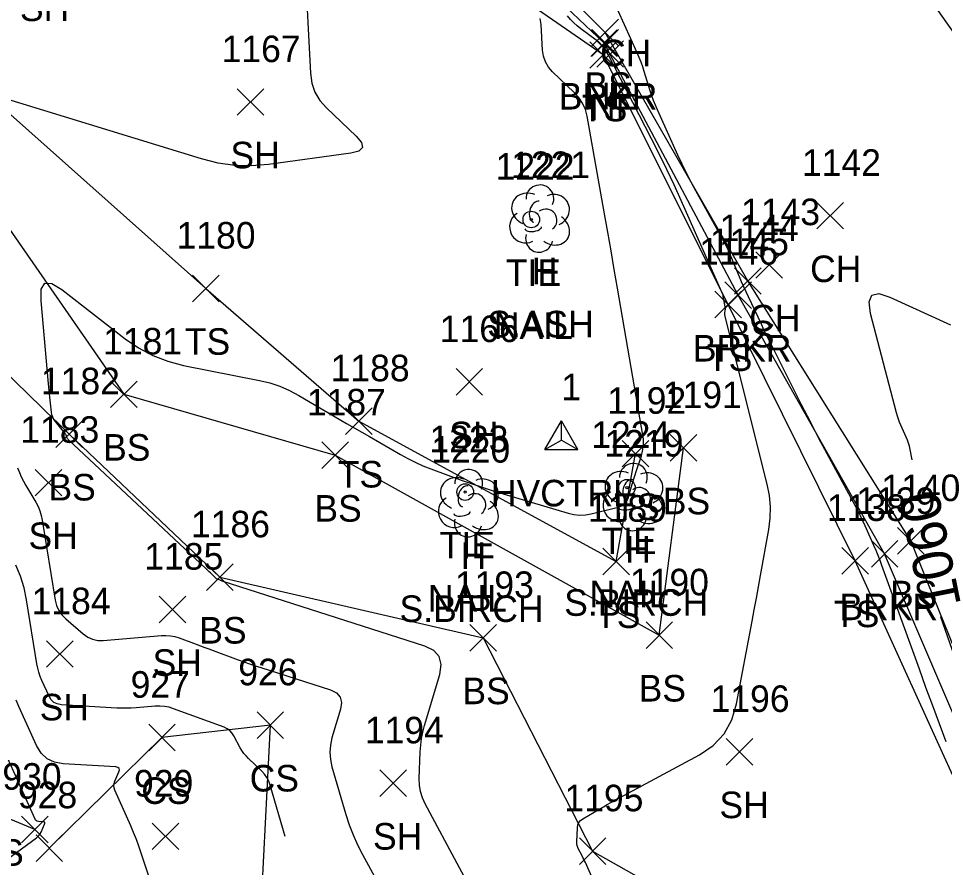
# Model space of a CAD drawing. Extents: x 1592612 to 1596497, y 111838 to 113741.
# Drawn here: x 1592722.3 to 1592792, y 113603.3 to 113667.2 of the extents above; entities that cross this region are included whole.
import ezdxf

# ---------------------------------------------------------------- set-up
doc = ezdxf.new("R2010")
doc.units = 0
for name, color, linetype in [('C_A', 7, 'Continuous'), ('C_C', 7, 'Continuous'), ('C_I', 7, 'Continuous'), ('CBP', 7, 'Continuous'), ('CPSM', 7, 'Continuous'), ('L_A', 7, 'Continuous'), ('L_C', 7, 'Continuous'), ('L_I', 7, 'Continuous'), ('L_TIC', 7, 'Continuous'), ('LAWE', 7, 'Continuous'), ('LELB', 7, 'Continuous'), ('LSOGCMA', 7, 'Continuous'), ('LSOGCMA_T', 7, 'Continuous'), ('LSOGCMI', 7, 'Continuous'), ('LTD', 7, 'Continuous'), ('LWS', 7, 'Continuous')]:
    doc.layers.add(name, color=color, linetype=linetype)

msp = doc.modelspace()

# ---------------------------------------------------------------- linework, layer by layer
at = {"layer": 'CBP'}
for centre, radius in [((1592760.904, 113652.058), 0.625), ((1592760.904, 113652.058), 0.0833), ((1592755.926, 113631.531), 0.625), ((1592768.105, 113631.854), 0.625), ((1592768.105, 113631.854), 0.0833), ((1592755.926, 113631.531), 0.0833)]:
    msp.add_circle(centre, radius, dxfattribs=at)
at = {"layer": 'CPSM'}
for p, q in [((1592761.919, 113634.729), (1592763.169, 113636.894)), ((1592764.419, 113634.729), (1592763.169, 113636.894)), ((1592763.169, 113635.45), (1592763.169, 113636.894)), ((1592761.919, 113634.729), (1592763.169, 113635.45)), ((1592763.169, 113635.45), (1592763.169, 113635.45)), ((1592763.169, 113635.45), (1592764.419, 113634.729)), ((1592761.919, 113634.729), (1592764.419, 113634.729))]:
    msp.add_line(p, q, dxfattribs=at)
at = {"layer": 'L_TIC'}
for points in [[(1592765.461, 113665.146), (1592767.461, 113667.146)], [(1592767.461, 113665.146), (1592765.461, 113667.146)], [(1592765.38, 113664.342), (1592767.38, 113666.342)], [(1592767.38, 113664.342), (1592765.38, 113666.342)], [(1592765.472, 113664.357), (1592767.472, 113666.357)], [(1592767.472, 113664.357), (1592765.472, 113666.357)], [(1592765.309, 113663.453), (1592767.309, 113665.453)], [(1592767.309, 113663.453), (1592765.309, 113665.453)], [(1592765.841, 113663.52), (1592767.841, 113665.52)], [(1592767.841, 113663.52), (1592765.841, 113665.52)], [(1592738.755, 113659.911), (1592740.755, 113661.911)], [(1592740.755, 113659.911), (1592738.755, 113661.911)], [(1592782.413, 113651.345), (1592784.413, 113653.345)], [(1592784.413, 113651.345), (1592782.413, 113653.345)], [(1592777.824, 113647.632), (1592779.824, 113649.632)], [(1592779.824, 113647.632), (1592777.824, 113649.632)], [(1592776.21, 113646.427), (1592778.21, 113648.427)], [(1592778.21, 113646.427), (1592776.21, 113648.427)], [(1592735.398, 113645.87), (1592737.398, 113647.87)], [(1592737.398, 113645.87), (1592735.398, 113647.87)], [(1592775.477, 113645.362), (1592777.477, 113647.362)], [(1592777.477, 113645.362), (1592775.477, 113647.362)], [(1592774.723, 113644.654), (1592776.723, 113646.654)], [(1592776.723, 113644.654), (1592774.723, 113646.654)], [(1592755.238, 113638.828), (1592757.238, 113640.828)], [(1592757.238, 113638.828), (1592755.238, 113640.828)], [(1592729.214, 113637.893), (1592731.214, 113639.893)], [(1592731.214, 113637.893), (1592729.214, 113639.893)], [(1592746.918, 113635.873), (1592748.918, 113637.873)], [(1592748.918, 113635.873), (1592746.918, 113637.873)], [(1592725.097, 113634.895), (1592727.097, 113636.895)], [(1592727.097, 113634.895), (1592725.097, 113636.895)], [(1592767.748, 113633.425), (1592769.748, 113635.425)], [(1592769.748, 113633.425), (1592767.748, 113635.425)], [(1592771.366, 113633.853), (1592773.366, 113635.853)], [(1592773.366, 113633.853), (1592771.366, 113635.853)], [(1592745.126, 113633.301), (1592747.126, 113635.301)], [(1592747.126, 113633.301), (1592745.126, 113635.301)], [(1592723.547, 113631.239), (1592725.547, 113633.239)], [(1592725.547, 113631.239), (1592723.547, 113633.239)], [(1592788.48, 113626.849), (1592790.48, 113628.849)], [(1592790.48, 113626.849), (1592788.48, 113628.849)], [(1592786.513, 113625.88), (1592788.513, 113627.88)], [(1592788.513, 113625.88), (1592786.513, 113627.88)], [(1592766.3, 113625.295), (1592768.3, 113627.295)], [(1592768.3, 113625.295), (1592766.3, 113627.295)], [(1592784.293, 113625.354), (1592786.293, 113627.354)], [(1592786.293, 113625.354), (1592784.293, 113627.354)], [(1592736.453, 113624.119), (1592738.453, 113626.119)], [(1592738.453, 113624.119), (1592736.453, 113626.119)], [(1592732.89, 113621.685), (1592734.89, 113623.685)], [(1592734.89, 113621.685), (1592732.89, 113623.685)], [(1592756.272, 113619.552), (1592758.272, 113621.552)], [(1592758.272, 113619.552), (1592756.272, 113621.552)], [(1592769.546, 113619.752), (1592771.546, 113621.752)], [(1592771.546, 113619.752), (1592769.546, 113621.752)], [(1592724.393, 113618.332), (1592726.393, 113620.332)], [(1592726.393, 113618.332), (1592724.393, 113620.332)], [(1592740.254, 113612.977), (1592742.254, 113614.977)], [(1592742.254, 113612.977), (1592740.254, 113614.977)], [(1592732.09, 113612.041), (1592734.09, 113614.041)], [(1592734.09, 113612.041), (1592732.09, 113614.041)], [(1592775.587, 113610.968), (1592777.587, 113612.968)], [(1592777.587, 113610.968), (1592775.587, 113612.968)], [(1592749.494, 113608.601), (1592751.494, 113610.601)], [(1592751.494, 113608.601), (1592749.494, 113610.601)], [(1592722.518, 113605.111), (1592724.518, 113607.111)], [(1592724.518, 113605.111), (1592722.518, 113607.111)], [(1592732.36, 113604.599), (1592734.36, 113606.599)], [(1592734.36, 113604.599), (1592732.36, 113606.599)], [(1592723.603, 113603.715), (1592725.603, 113605.715)], [(1592725.603, 113603.715), (1592723.603, 113605.715)], [(1592764.525, 113603.487), (1592766.525, 113605.487)], [(1592766.525, 113603.487), (1592764.525, 113605.487)]]:
    msp.add_lwpolyline(points, dxfattribs=at)
at = {"layer": 'LAWE'}
msp.add_lwpolyline([(1592867.645, 113460.38), (1592859.409, 113477.515), (1592844.793, 113495.549), (1592832.37, 113516.6), (1592826.928, 113530.545), (1592818.762, 113547.936), (1592807.597, 113581.108), (1592797.669, 113603.177), (1592787.513, 113626.88), (1592776.477, 113646.362), (1592766.38, 113665.342), (1592748.736, 113682.085), (1592730.356, 113695.945)], dxfattribs=at)
at = {"layer": 'LELB'}
for points in [[(1592869.098, 113460.398), (1592860.441, 113478.115), (1592844.631, 113496.556), (1592834.165, 113516.964), (1592828.396, 113531.171), (1592823.559, 113549.918), (1592808.456, 113581.723), (1592799.527, 113603.061), (1592789.48, 113627.849), (1592777.21, 113647.427), (1592766.461, 113666.146), (1592749.422, 113683.288), (1592730.933, 113697.021)], [(1592856.492, 113476.867), (1592843.193, 113495.045), (1592831.688, 113516.664), (1592823.204, 113528.692), (1592814.853, 113545.459), (1592806.797, 113580.845), (1592796.452, 113601.854), (1592785.293, 113626.354), (1592775.723, 113645.654), (1592766.309, 113664.453), (1592745.043, 113679.184), (1592727.847, 113694.217)], [(1592709.84, 113681.357), (1592717.065, 113664.051), (1592736.398, 113646.87), (1592747.918, 113636.873), (1592767.3, 113626.295), (1592768.748, 113634.425)], [(1592705.057, 113678.307), (1592714.096, 113662.114), (1592730.214, 113638.893), (1592746.126, 113634.3), (1592770.546, 113620.752), (1592772.366, 113634.853)], [(1592701.588, 113659.774), (1592726.097, 113635.895), (1592737.453, 113625.119), (1592757.272, 113620.552), (1592765.525, 113604.487), (1592785.217, 113593.362), (1592785.143, 113579.955), (1592783.097, 113567.939), (1592785.828, 113560.008), (1592797.4, 113544.62), (1592809.213, 113533.643), (1592811.425, 113524.524), (1592820.841, 113522.69), (1592826.429, 113512.914)], [(1592733.8, 113592.586), (1592740.378, 113596.74), (1592741.254, 113613.977), (1592733.09, 113613.041), (1592724.603, 113604.715)]]:
    msp.add_lwpolyline(points, dxfattribs=at)
at = {"layer": 'LSOGCMA'}
for points in [[(1592789.576, 113633.948), (1592789.433, 113634.735), (1592789.382, 113634.975), (1592789.316, 113635.211), (1592789.236, 113635.442), (1592789.141, 113635.669), (1592788.732, 113636.567), (1592788.635, 113636.793), (1592788.548, 113637.023), (1592788.471, 113637.256), (1592788.404, 113637.493), (1592786.456, 113644.984), (1592786.339, 113645.863), (1592786.542, 113646.36), (1592787.067, 113646.476), (1592787.913, 113646.209), (1592792.467, 113644.137)], [(1592742.366, 113605.578), (1592741.233, 113609.455), (1592741.127, 113609.749), (1592740.985, 113610.022), (1592740.809, 113610.274), (1592740.598, 113610.504), (1592739.595, 113611.468), (1592739.418, 113611.652), (1592739.257, 113611.848), (1592739.111, 113612.056), (1592738.982, 113612.276), (1592738.494, 113613.18), (1592738.357, 113613.389), (1592738.191, 113613.564), (1592737.995, 113613.704), (1592737.769, 113613.81), (1592733.967, 113615.212), (1592733.626, 113615.317), (1592733.28, 113615.384), (1592732.929, 113615.412), (1592732.573, 113615.402), (1592731.138, 113615.282), (1592730.779, 113615.259), (1592730.42, 113615.248), (1592730.061, 113615.251), (1592729.701, 113615.265), (1592725.512, 113615.513), (1592725.208, 113615.567), (1592724.953, 113615.692), (1592724.745, 113615.886), (1592724.586, 113616.149), (1592724.044, 113617.345), (1592723.919, 113617.647), (1592723.814, 113617.955), (1592723.731, 113618.269), (1592723.668, 113618.59), (1592722.89, 113623.418), (1592722.702, 113624.316), (1592722.434, 113625.185), (1592722.084, 113626.025)], [(1592797.582, 113605.486), (1592791.75, 113622.113), (1592791.741, 113622.143)]]:
    msp.add_lwpolyline(points, dxfattribs=at)
at = {"layer": 'LSOGCMI'}
for points in [[(1592788.325, 113672.344), (1592793.937, 113664.383)], [(1592743.845, 113671.231), (1592744.267, 113663.072), (1592744.372, 113662.328), (1592744.608, 113661.644), (1592744.975, 113661.021), (1592745.473, 113660.458), (1592747.724, 113658.327), (1592748.12, 113657.847), (1592748.184, 113657.475), (1592747.915, 113657.21), (1592747.314, 113657.052), (1592741.123, 113656.21), (1592739.841, 113656.104), (1592738.57, 113656.137), (1592737.31, 113656.31), (1592736.062, 113656.622), (1592720.725, 113661.329)], [(1592792.151, 113612.707), (1592791.639, 113614.073), (1592791.132, 113615.441), (1592790.629, 113616.811), (1592790.131, 113618.182), (1592787.307, 113626.001), (1592787.166, 113626.382), (1592787.018, 113626.761), (1592786.864, 113627.136), (1592786.703, 113627.51), (1592786.045, 113628.997), (1592785.877, 113629.367), (1592785.702, 113629.734), (1592785.52, 113630.096), (1592785.33, 113630.456), (1592783.017, 113634.74), (1592782.57, 113635.574), (1592782.129, 113636.412), (1592781.694, 113637.253), (1592781.264, 113638.097), (1592779.14, 113642.31), (1592778.908, 113642.773), (1592778.679, 113643.238), (1592778.454, 113643.704), (1592778.231, 113644.171), (1592777.258, 113646.227), (1592777.082, 113646.604), (1592776.911, 113646.983), (1592776.744, 113647.365), (1592776.582, 113647.748), (1592775.942, 113649.285), (1592775.776, 113649.667), (1592775.6, 113650.044), (1592775.413, 113650.415), (1592775.215, 113650.781), (1592773.292, 113654.215), (1592772.932, 113654.875), (1592772.587, 113655.543), (1592772.256, 113656.217), (1592771.939, 113656.9), (1592770.397, 113660.32), (1592770.246, 113660.669), (1592770.106, 113661.022), (1592769.977, 113661.38), (1592769.86, 113661.742), (1592769.412, 113663.197), (1592769.295, 113663.559), (1592769.166, 113663.916), (1592769.026, 113664.269), (1592768.875, 113664.618), (1592767.447, 113667.774)], [(1592758.081, 113598.41), (1592752.906, 113608.054), (1592752.7, 113608.506), (1592752.558, 113608.972), (1592752.481, 113609.453), (1592752.467, 113609.949), (1592752.542, 113611.963), (1592752.576, 113612.464), (1592752.641, 113612.96), (1592752.737, 113613.451), (1592752.865, 113613.937), (1592754.005, 113617.797), (1592754.113, 113618.533), (1592753.962, 113619.132), (1592753.552, 113619.594), (1592752.883, 113619.92), (1592737.621, 113624.831), (1592737.582, 113624.843), (1592737.543, 113624.857), (1592737.504, 113624.87), (1592737.465, 113624.884), (1592737.311, 113624.941), (1592737.273, 113624.957), (1592737.238, 113624.977), (1592737.205, 113625), (1592737.174, 113625.026), (1592736.732, 113625.449), (1592736.648, 113625.529), (1592736.564, 113625.609), (1592736.48, 113625.688), (1592736.396, 113625.768), (1592726.021, 113635.498), (1592725.99, 113635.53), (1592725.964, 113635.566), (1592725.942, 113635.604), (1592725.925, 113635.645), (1592725.866, 113635.816), (1592725.849, 113635.858), (1592725.829, 113635.898), (1592725.806, 113635.936), (1592725.779, 113635.971), (1592725.067, 113636.837), (1592724.952, 113636.998), (1592724.864, 113637.171), (1592724.802, 113637.354), (1592724.767, 113637.549), (1592724.647, 113638.673), (1592724.62, 113638.928), (1592724.594, 113639.182), (1592724.57, 113639.437), (1592724.546, 113639.691), (1592723.98, 113645.922), (1592724.003, 113646.818), (1592724.273, 113647.26), (1592724.791, 113647.249), (1592725.557, 113646.783), (1592730.32, 113643.078), (1592731.329, 113642.381), (1592732.397, 113641.814), (1592733.524, 113641.378), (1592734.711, 113641.071), (1592740.431, 113639.934), (1592741.208, 113639.745), (1592741.962, 113639.495), (1592742.692, 113639.181), (1592743.398, 113638.805), (1592746.422, 113637.032), (1592746.993, 113636.698), (1592747.564, 113636.365), (1592748.136, 113636.034), (1592748.709, 113635.703), (1592751.051, 113634.355), (1592751.605, 113634.051), (1592752.17, 113633.772), (1592752.747, 113633.517), (1592753.335, 113633.286), (1592755.709, 113632.411), (1592756.304, 113632.197), (1592756.902, 113631.991), (1592757.503, 113631.795), (1592758.107, 113631.608), (1592763.675, 113629.928), (1592764.11, 113629.828), (1592764.546, 113629.788), (1592764.984, 113629.809), (1592765.423, 113629.89), (1592767.546, 113630.429), (1592767.779, 113630.518), (1592767.967, 113630.655), (1592768.108, 113630.839), (1592768.203, 113631.07), (1592768.498, 113632.12), (1592768.568, 113632.359), (1592768.64, 113632.598), (1592768.715, 113632.835), (1592768.794, 113633.072), (1592769.199, 113634.264), (1592769.234, 113634.376), (1592769.262, 113634.49), (1592769.284, 113634.606), (1592769.299, 113634.723), (1592769.348, 113635.194), (1592769.356, 113635.312), (1592769.356, 113635.429), (1592769.348, 113635.546), (1592769.332, 113635.663), (1592767.398, 113646.894), (1592767.156, 113648.296), (1592766.911, 113649.697), (1592766.665, 113651.097), (1592766.416, 113652.498), (1592765.107, 113659.841), (1592764.975, 113660.349), (1592764.77, 113660.818), (1592764.491, 113661.247), (1592764.138, 113661.636), (1592762.501, 113663.186), (1592762.191, 113663.538), (1592761.962, 113663.927), (1592761.814, 113664.353), (1592761.749, 113664.817), (1592761.649, 113666.75), (1592761.579, 113667.208)], [(1592766.646, 113599.856), (1592764.98, 113603.628), (1592764.921, 113603.758), (1592764.86, 113603.887), (1592764.796, 113604.014), (1592764.73, 113604.141), (1592764.46, 113604.644), (1592764.402, 113604.771), (1592764.362, 113604.903), (1592764.34, 113605.04), (1592764.336, 113605.18), (1592764.375, 113606.243), (1592764.407, 113606.454), (1592764.485, 113606.637), (1592764.609, 113606.793), (1592764.78, 113606.921), (1592766.055, 113607.671), (1592766.332, 113607.833), (1592766.612, 113607.992), (1592766.893, 113608.148), (1592767.175, 113608.302), (1592773.564, 113611.744), (1592774.609, 113612.452), (1592775.424, 113613.327), (1592776.01, 113614.37), (1592776.367, 113615.581), (1592777.534, 113621.808), (1592777.695, 113622.669), (1592777.854, 113623.53), (1592778.012, 113624.391), (1592778.169, 113625.253), (1592778.793, 113628.699), (1592778.903, 113629.559), (1592778.92, 113630.417), (1592778.845, 113631.27), (1592778.678, 113632.121), (1592775.506, 113644.746), (1592775.494, 113644.804), (1592775.487, 113644.862), (1592775.485, 113644.921), (1592775.489, 113644.98), (1592775.514, 113645.224), (1592775.518, 113645.28), (1592775.518, 113645.335), (1592775.514, 113645.391), (1592775.506, 113645.447), (1592775.468, 113645.669), (1592775.458, 113645.724), (1592775.449, 113645.78), (1592775.439, 113645.835), (1592775.429, 113645.891), (1592775.361, 113646.271), (1592775.344, 113646.352), (1592775.322, 113646.432), (1592775.296, 113646.51), (1592775.264, 113646.587), (1592772.191, 113653.497), (1592771.659, 113654.671), (1592771.11, 113655.836), (1592770.545, 113656.993), (1592769.963, 113658.142), (1592766.692, 113664.493), (1592766.512, 113664.798), (1592766.302, 113665.078), (1592766.06, 113665.331), (1592765.788, 113665.559), (1592764.639, 113666.416), (1592764.36, 113666.639), (1592764.097, 113666.878), (1592763.851, 113667.135), (1592763.621, 113667.409)], [(1592722.22, 113633.354), (1592722.349, 113633.01), (1592722.494, 113632.675), (1592722.656, 113632.347), (1592722.835, 113632.027), (1592723.585, 113630.762), (1592723.756, 113630.44), (1592723.895, 113630.107), (1592724.001, 113629.761), (1592724.076, 113629.405), (1592725.045, 113623.392), (1592725.146, 113622.983), (1592725.313, 113622.61), (1592725.544, 113622.274), (1592725.84, 113621.975), (1592727.153, 113620.849), (1592727.494, 113620.607), (1592727.861, 113620.444), (1592728.254, 113620.361), (1592728.672, 113620.357), (1592733.049, 113620.721), (1592733.388, 113620.731), (1592733.722, 113620.704), (1592734.051, 113620.64), (1592734.376, 113620.54), (1592735.662, 113620.066), (1592735.984, 113619.947), (1592736.306, 113619.828), (1592736.628, 113619.71), (1592736.949, 113619.591), (1592738.838, 113618.896), (1592739.26, 113618.743), (1592739.685, 113618.594), (1592740.11, 113618.45), (1592740.538, 113618.31), (1592745.779, 113616.624), (1592746.23, 113616.404), (1592746.507, 113616.092), (1592746.609, 113615.687), (1592746.536, 113615.19), (1592745.894, 113613.018), (1592745.774, 113612.474), (1592745.733, 113611.931), (1592745.772, 113611.387), (1592745.891, 113610.844), (1592746.945, 113607.236), (1592747.194, 113606.462), (1592747.484, 113605.704), (1592747.814, 113604.964), (1592748.184, 113604.24), (1592751.46, 113598.245)], [(1592733.205, 113599.295), (1592731.532, 113604.332), (1592731.352, 113604.853), (1592731.159, 113605.37), (1592730.955, 113605.882), (1592730.737, 113606.389), (1592729.55, 113609.074), (1592729.493, 113609.246), (1592729.473, 113609.419), (1592729.492, 113609.591), (1592729.548, 113609.764), (1592729.848, 113610.456), (1592729.89, 113610.609), (1592729.866, 113610.721), (1592729.777, 113610.793), (1592729.621, 113610.824), (1592725.65, 113611.059), (1592724.993, 113611.177), (1592724.439, 113611.446), (1592723.99, 113611.866), (1592723.644, 113612.438), (1592722.305, 113615.391), (1592722.11, 113615.861)], [(1592721.015, 113603.555), (1592723.644, 113605.489), (1592723.75, 113605.578), (1592723.842, 113605.679), (1592723.92, 113605.791), (1592723.984, 113605.915), (1592724.249, 113606.528), (1592724.269, 113606.6), (1592724.258, 113606.654), (1592724.216, 113606.688), (1592724.142, 113606.702), (1592723.785, 113606.724), (1592723.702, 113606.738), (1592723.632, 113606.772), (1592723.576, 113606.825), (1592723.532, 113606.897), (1592720.074, 113614.523)]]:
    msp.add_lwpolyline(points, dxfattribs=at)
at = {"layer": 'LTD'}
for p, q in [((1592761.508, 113652.18), (1592761.508, 113652.18)), ((1592761.508, 113652.18), (1592761.508, 113652.18)), ((1592756.147, 113630.745), (1592756.147, 113630.745)), ((1592756.147, 113630.745), (1592756.147, 113630.745)), ((1592768.546, 113631.208), (1592768.546, 113631.208)), ((1592768.546, 113631.208), (1592768.546, 113631.208))]:
    msp.add_line(p, q, dxfattribs=at)
for centre in [(1592761.554, 113653.614), (1592768.593, 113632.642), (1592756.194, 113632.179)]:
    msp.add_arc(centre, 1.047, 335.52715, 180.95627, dxfattribs=at)
for centre, major_axis, ratio, start_param, end_param in [((1592760.716, 113652.847), (1.21, -0.512), 0.895232, 1.570796, 4.712389), ((1592762.549, 113652.764), (-1.141, -0.483), 0.949671, 1.570796, 4.712389), ((1592761.299, 113652.638), (-0.208, -0.792), 0.645439, 3.141593, 6.283185), ((1592762.008, 113652.014), (-0.5, 0.667), 0.989748, 3.141593, 6.283185), ((1592760.424, 113651.472), (0.584, -1.042), 0.959034, 3.141593, 6.283185), ((1592762.508, 113651.347), (-1.09, 0.792), 0.841452, 1.570796, 4.712389), ((1592761.049, 113651.43), (-0.625, -0.083), 0.423636, 0, 3.141593), ((1592761.508, 113650.68), (0.265, 1.061), 0.942809, 1.570796, 4.712389), ((1592755.355, 113631.412), (1.21, -0.512), 0.895232, 1.570796, 4.712389), ((1592757.188, 113631.329), (-1.141, -0.483), 0.949671, 1.570796, 4.712389), ((1592767.754, 113631.875), (1.21, -0.512), 0.895232, 1.570796, 4.712389), ((1592769.588, 113631.792), (-1.141, -0.483), 0.949671, 1.570796, 4.712389), ((1592755.938, 113631.204), (-0.208, -0.792), 0.645439, 3.141593, 6.283185), ((1592768.338, 113631.667), (-0.208, -0.792), 0.645439, 3.141593, 6.283185), ((1592769.046, 113631.042), (-0.5, 0.667), 0.989748, 3.141593, 6.283185), ((1592756.647, 113630.579), (-0.5, 0.667), 0.989748, 3.141593, 6.283185), ((1592767.463, 113630.5), (0.584, -1.042), 0.959034, 3.141593, 6.283185), ((1592769.546, 113630.375), (-1.09, 0.792), 0.841452, 1.570796, 4.712389), ((1592755.064, 113630.037), (0.584, -1.042), 0.959034, 3.141593, 6.283185), ((1592757.147, 113629.912), (-1.09, 0.792), 0.841452, 1.570796, 4.712389), ((1592768.088, 113630.458), (-0.625, -0.083), 0.423636, 0, 3.141593), ((1592755.689, 113629.995), (-0.625, -0.083), 0.423636, 0, 3.141593), ((1592768.546, 113629.708), (0.265, 1.061), 0.942809, 1.570796, 4.712389), ((1592756.147, 113629.245), (0.265, 1.061), 0.942809, 1.570796, 4.712389)]:
    msp.add_ellipse(centre, major_axis=major_axis, ratio=ratio, start_param=start_param, end_param=end_param, dxfattribs=at)
at = {"layer": 'LWS'}
msp.add_lwpolyline([(1592723.518, 113606.111), (1592718.067, 113608.381), (1592705.094, 113621.183)], dxfattribs=at)

# ---------------------------------------------------------------- texts
at = {"layer": 'C_A'}
for s, p in [('TIE', (1592758.983, 113647.058)), ('HVCTRL', (1592757.862, 113630.45)), ('TIE', (1592754.005, 113626.531)), ('TIE', (1592766.184, 113626.854))]:
    msp.add_text(s, height=2, dxfattribs=at).set_placement(p)
at = {"layer": 'C_C'}
for p in [(1592758.085, 113643.058), (1592753.108, 113622.531), (1592765.287, 113622.854)]:
    msp.add_text('NAIL', height=2, dxfattribs=at).set_placement(p)
at = {"layer": 'C_I'}
for s, p in [('1222', (1592758.211, 113655.058)), ('1', (1592763.169, 113638.45)), ('1224', (1592765.413, 113634.854)), ('1223', (1592753.234, 113634.531))]:
    msp.add_text(s, height=2, dxfattribs=at).set_placement(p)
at = {"layer": 'L_A'}
for s, p in [('SH', (1592722.39, 113667.003)), ('CH', (1592766.079, 113663.601)), ('BS', (1592764.902, 113661.146)), ('BRKR', (1592762.971, 113660.342)), ('NF', (1592764.952, 113660.357)), ('TS', (1592764.718, 113659.453)), ('NF', (1592765.321, 113659.52)), ('SH', (1592738.243, 113655.911)), ('CH', (1592781.901, 113647.345)), ('H', (1592760.941, 113647.18)), ('CH', (1592777.313, 113643.632)), ('TS', (1592734.808, 113641.87)), ('BS', (1592775.651, 113642.427)), ('BRKR', (1592773.068, 113641.362)), ('TS', (1592774.133, 113640.654)), ('SH', (1592754.726, 113634.828)), ('BS', (1592728.655, 113633.893)), ('TS', (1592746.328, 113631.873)), ('BS', (1592724.538, 113630.895)), ('BS', (1592744.567, 113629.301)), ('TS', (1592767.157, 113629.425)), ('BS', (1592770.807, 113629.853)), ('SH', (1592723.036, 113627.239)), ('H', (1592755.58, 113625.745)), ('H', (1592767.979, 113626.208)), ('BS', (1592787.921, 113622.849)), ('BRKR', (1592784.104, 113621.88)), ('TS', (1592765.709, 113621.295)), ('TS', (1592783.702, 113621.354)), ('BS', (1592735.894, 113620.119)), ('SH', (1592732.379, 113617.685)), ('BS', (1592755.713, 113615.552)), ('BS', (1592768.987, 113615.752)), ('SH', (1592723.881, 113614.332)), ('CS', (1592739.695, 113608.977)), ('CS', (1592731.531, 113608.041)), ('SH', (1592775.075, 113606.968)), ('SH', (1592748.982, 113604.601)), ('WALLS', (1592713.611, 113603.381))]:
    msp.add_text(s, height=2, dxfattribs=at).set_placement(p)
at = {"layer": 'L_C'}
for s, p in [('S.ASH', (1592757.586, 113643.18)), ('S.BIRCH', (1592750.981, 113621.745)), ('S.BIRCH', (1592763.381, 113622.208))]:
    msp.add_text(s, height=2, dxfattribs=at).set_placement(p)
at = {"layer": 'L_I'}
for s, p in [('1167', (1592737.581, 113663.911)), ('1221', (1592759.382, 113655.18)), ('1142', (1592781.287, 113655.345)), ('1143', (1592776.699, 113651.632)), ('1144', (1592775.084, 113650.427)), ('1180', (1592734.186, 113649.87)), ('1145', (1592774.351, 113649.362)), ('1146', (1592773.542, 113648.654)), ('1166', (1592754.009, 113642.828)), ('1181', (1592728.655, 113641.893)), ('1188', (1592745.792, 113639.873)), ('1182', (1592723.971, 113638.895)), ('1191', (1592770.807, 113637.853)), ('1187', (1592744, 113637.301)), ('1192', (1592766.622, 113637.425)), ('1183', (1592722.422, 113635.239)), ('1219', (1592766.412, 113634.208)), ('1220', (1592753.367, 113633.745)), ('1140', (1592787.268, 113630.849)), ('1189', (1592765.166, 113629.295)), ('1138', (1592783.167, 113629.354)), ('1139', (1592785.379, 113629.88)), ('1186', (1592735.272, 113628.119)), ('1185', (1592731.764, 113625.685)), ('1190', (1592768.333, 113623.752)), ('1193', (1592755.146, 113623.552)), ('1184', (1592723.267, 113622.332)), ('926', (1592738.837, 113616.977)), ('927', (1592730.728, 113616.041)), ('1196', (1592774.406, 113614.968)), ('1194', (1592748.368, 113612.601)), ('930', (1592721.069, 113609.111)), ('929', (1592730.99, 113608.599)), ('928', (1592722.241, 113607.715)), ('1195', (1592763.399, 113607.487))]:
    msp.add_text(s, height=2, dxfattribs=at).set_placement(p)
at = {"layer": 'LSOGCMA_T'}
msp.add_text('1060', height=3, rotation=101.43171, dxfattribs=at).set_placement((1592793.28, 113623.033))

doc.saveas('drawing.dxf')
